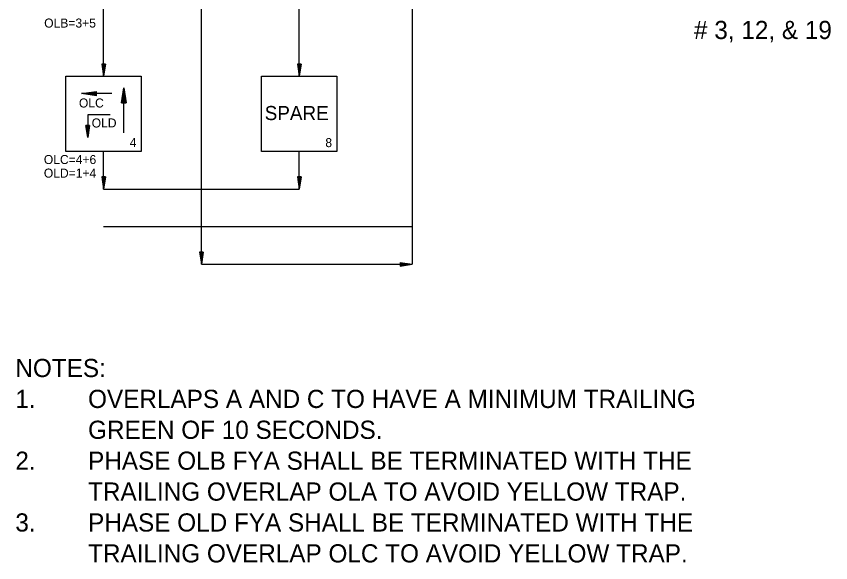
# Model space of a CAD drawing. Extents: x -218554 to 420030, y -566264 to -483460.
# Drawn here: x 418144.4 to 418332.6, y -565562.1 to -565435.8 of the extents above; entities that cross this region are included whole.
import ezdxf

# ---------------------------------------------------------------- set-up
doc = ezdxf.new("R2010")
doc.units = 0
doc.layers.add('G-ANNO-STMP', color=7, linetype='Continuous')
doc.layers.add('Level 57', color=7, linetype='Continuous')

msp = doc.modelspace()

# ---------------------------------------------------------------- linework, layer by layer
at = {"layer": 'Level 57'}
for p, q in [((418187.2, -565493.1), (418187.2, -565310.48)), ((418235.9, -565310.48), (418235.9, -565493.1)), ((418164.59, -565449.62), (418164.59, -565432.22)), ((418209.81, -565449.62), (418209.81, -565432.22)), ((418164.18, -565446.83), (418164.59, -565449.62)), ((418165.01, -565446.83), (418164.18, -565446.83)), ((418164.25, -565446.83), (418164.59, -565449.15)), ((418164.32, -565446.83), (418164.59, -565448.67)), ((418164.39, -565446.83), (418164.59, -565448.21)), ((418164.46, -565446.83), (418164.59, -565447.74)), ((418164.53, -565446.83), (418164.59, -565447.27)), ((418165.01, -565446.83), (418164.59, -565449.62)), ((418164.73, -565446.83), (418164.59, -565447.74)), ((418164.87, -565446.83), (418164.59, -565448.67)), ((418164.94, -565446.83), (418164.59, -565449.15)), ((418164.8, -565446.83), (418164.59, -565448.21)), ((418164.66, -565446.83), (418164.59, -565447.27)), ((418209.4, -565446.83), (418209.81, -565449.62)), ((418210.23, -565446.83), (418209.4, -565446.83)), ((418209.47, -565446.83), (418209.81, -565449.15)), ((418209.54, -565446.83), (418209.81, -565448.67)), ((418209.61, -565446.83), (418209.81, -565448.21)), ((418209.68, -565446.83), (418209.81, -565447.74)), ((418209.75, -565446.83), (418209.81, -565447.27)), ((418210.23, -565446.83), (418209.81, -565449.62)), ((418209.95, -565446.83), (418209.81, -565447.74)), ((418210.09, -565446.83), (418209.81, -565448.67)), ((418210.16, -565446.83), (418209.81, -565449.15)), ((418210.02, -565446.83), (418209.81, -565448.21)), ((418209.88, -565446.83), (418209.81, -565447.27)), ((418168.75, -565455.76), (418169.28, -565452.29)), ((418169.28, -565462.72), (418169.28, -565452.29)), ((418169.28, -565452.29), (418169.8, -565455.76)), ((418159.46, -565453.65), (418162.94, -565453.13)), ((418166.51, -565453.65), (418159.46, -565453.65)), ((418162.94, -565454.17), (418159.46, -565453.65)), ((418162.94, -565453.22), (418160.04, -565453.65)), ((418160.04, -565453.65), (418162.94, -565454.09)), ((418160.64, -565453.65), (418162.94, -565453.31)), ((418162.94, -565454), (418160.64, -565453.65)), ((418162.94, -565453.39), (418161.22, -565453.65)), ((418161.22, -565453.65), (418162.94, -565453.91)), ((418161.8, -565453.65), (418162.94, -565453.48)), ((418162.94, -565453.82), (418161.8, -565453.65)), ((418162.94, -565453.57), (418162.39, -565453.65)), ((418162.39, -565453.65), (418162.94, -565453.73)), ((418162.94, -565454.17), (418162.94, -565453.13)), ((418169.28, -565452.87), (418168.84, -565455.76)), ((418168.93, -565455.76), (418169.28, -565453.47)), ((418169.28, -565454.04), (418169.02, -565455.76)), ((418169.71, -565455.76), (418169.28, -565452.87)), ((418169.28, -565453.47), (418169.62, -565455.76)), ((418169.53, -565455.76), (418169.28, -565454.04)), ((418168.75, -565455.76), (418169.8, -565455.76)), ((418169.11, -565455.76), (418169.28, -565454.63)), ((418169.28, -565455.21), (418169.19, -565455.76)), ((418169.28, -565454.63), (418169.45, -565455.76)), ((418169.36, -565455.76), (418169.28, -565455.21)), ((418166.15, -565458.59), (418160.93, -565458.59)), ((418160.93, -565458.59), (418160.93, -565463.81)), ((418160.93, -565463.81), (418160.51, -565461.02)), ((418161.35, -565461.02), (418160.51, -565461.02)), ((418160.58, -565461.02), (418160.93, -565463.34)), ((418160.93, -565462.86), (418160.66, -565461.02)), ((418160.72, -565461.02), (418160.93, -565462.4)), ((418160.93, -565461.93), (418160.8, -565461.02)), ((418160.87, -565461.02), (418160.93, -565461.46)), ((418160.93, -565461.46), (418161, -565461.02)), ((418161.07, -565461.02), (418160.93, -565461.93)), ((418160.93, -565462.4), (418161.14, -565461.02)), ((418161.21, -565461.02), (418160.93, -565462.86)), ((418160.93, -565463.34), (418161.28, -565461.02)), ((418161.35, -565461.02), (418160.93, -565463.81)), ((418164.59, -565475.7), (418164.59, -565467.01)), ((418209.81, -565475.7), (418209.81, -565467.01)), ((418209.81, -565475.7), (418209.81, -565467.01)), ((418164.18, -565472.92), (418164.59, -565475.7)), ((418165.01, -565472.92), (418164.18, -565472.92)), ((418164.25, -565472.92), (418164.59, -565475.24)), ((418164.32, -565472.92), (418164.59, -565474.76)), ((418164.39, -565472.92), (418164.59, -565474.3)), ((418164.46, -565472.92), (418164.59, -565473.83)), ((418164.53, -565472.92), (418164.59, -565473.36)), ((418165.01, -565472.92), (418164.59, -565475.7)), ((418164.73, -565472.92), (418164.59, -565473.83)), ((418164.87, -565472.92), (418164.59, -565474.76)), ((418164.94, -565472.92), (418164.59, -565475.24)), ((418164.8, -565472.92), (418164.59, -565474.3)), ((418164.66, -565472.92), (418164.59, -565473.36)), ((418209.4, -565472.92), (418209.81, -565475.7)), ((418210.23, -565472.92), (418209.4, -565472.92)), ((418209.4, -565472.92), (418209.81, -565475.7)), ((418210.23, -565472.92), (418209.4, -565472.92)), ((418209.47, -565472.92), (418209.81, -565475.24)), ((418209.47, -565472.92), (418209.81, -565475.24)), ((418209.54, -565472.92), (418209.81, -565474.76)), ((418209.54, -565472.92), (418209.81, -565474.76)), ((418209.61, -565472.92), (418209.81, -565474.3)), ((418209.61, -565472.92), (418209.81, -565474.3)), ((418209.68, -565472.92), (418209.81, -565473.83)), ((418209.68, -565472.92), (418209.81, -565473.83)), ((418209.75, -565472.92), (418209.81, -565473.36)), ((418209.75, -565472.92), (418209.81, -565473.36)), ((418210.23, -565472.92), (418209.81, -565475.7)), ((418209.95, -565472.92), (418209.81, -565473.83)), ((418210.09, -565472.92), (418209.81, -565474.76)), ((418210.16, -565472.92), (418209.81, -565475.24)), ((418210.02, -565472.92), (418209.81, -565474.3)), ((418209.88, -565472.92), (418209.81, -565473.36)), ((418210.23, -565472.92), (418209.81, -565475.7)), ((418209.95, -565472.92), (418209.81, -565473.83)), ((418210.09, -565472.92), (418209.81, -565474.76)), ((418210.16, -565472.92), (418209.81, -565475.24)), ((418210.02, -565472.92), (418209.81, -565474.3)), ((418209.88, -565472.92), (418209.81, -565473.36)), ((418164.59, -565475.7), (418209.81, -565475.7)), ((418164.59, -565484.4), (418235.9, -565484.4)), ((418186.79, -565490.31), (418187.2, -565493.1)), ((418187.62, -565490.31), (418186.79, -565490.31)), ((418186.86, -565490.31), (418187.2, -565492.63)), ((418186.93, -565490.31), (418187.2, -565492.15)), ((418187, -565490.31), (418187.2, -565491.69)), ((418187.07, -565490.31), (418187.2, -565491.22)), ((418187.14, -565490.31), (418187.2, -565490.75)), ((418187.62, -565490.31), (418187.2, -565493.1)), ((418187.34, -565490.31), (418187.2, -565491.22)), ((418187.48, -565490.31), (418187.2, -565492.15)), ((418187.55, -565490.31), (418187.2, -565492.63)), ((418187.41, -565490.31), (418187.2, -565491.69)), ((418187.27, -565490.31), (418187.2, -565490.75)), ((418187.2, -565493.1), (418235.9, -565493.1)), ((418233.12, -565492.68), (418235.9, -565493.1)), ((418233.12, -565492.68), (418233.12, -565493.51)), ((418233.12, -565492.75), (418235.44, -565493.1)), ((418233.12, -565492.82), (418234.96, -565493.1)), ((418233.12, -565492.89), (418234.49, -565493.1)), ((418233.12, -565492.96), (418234.02, -565493.1)), ((418233.12, -565493.03), (418233.56, -565493.1)), ((418233.12, -565493.51), (418235.9, -565493.1)), ((418233.12, -565493.23), (418234.02, -565493.1)), ((418233.12, -565493.37), (418234.96, -565493.1)), ((418233.12, -565493.44), (418235.44, -565493.1)), ((418233.12, -565493.3), (418234.49, -565493.1)), ((418233.12, -565493.16), (418233.56, -565493.1))]:
    msp.add_line(p, q, dxfattribs=at)
for points in [[(418155.9, -565449.62), (418173.29, -565449.62), (418173.29, -565467.01), (418155.9, -565467.01)], [(418201.12, -565449.62), (418218.51, -565449.62), (418218.51, -565467.01), (418201.12, -565467.01)]]:
    msp.add_lwpolyline(points, close=True, dxfattribs=at)

# ---------------------------------------------------------------- texts
at = {"layer": 'G-ANNO-STMP'}
for s, p in [('# 3, 12, & 19', (418301.04, -565441.04)), ('NOTES:', (418144.21, -565519.17)), ('1.', (418144.21, -565526.31)), ('OVERLAPS A AND C TO HAVE A MINIMUM TRAILING', (418161.01, -565526.31)), ('GREEN OF 10 SECONDS.', (418161.01, -565533.45)), ('2.', (418144.21, -565540.59)), ('PHASE OLB FYA SHALL BE TERMINATED WITH THE', (418161.01, -565540.59)), ('TRAILING OVERLAP OLA TO AVOID YELLOW TRAP.', (418161.01, -565547.73)), ('3.', (418144.21, -565554.87)), ('PHASE OLD FYA SHALL BE TERMINATED WITH THE ', (418161.01, -565554.87)), ('TRAILING OVERLAP OLC TO AVOID YELLOW TRAP.', (418161.01, -565562.01))]:
    msp.add_text(s, height=4.2, dxfattribs=at).set_placement(p)
at = {"layer": 'Level 57'}
for s, height, p in [('OLB=3+5', 2.087, (418150.87, -565438.39)), ('OLC', 2.087, (418158.9, -565456.86)), ('SPARE', 3.261, (418201.83, -565459.77)), ('OLD', 2.087, (418161.85, -565461.48)), ('4', 2.09, (418170.62, -565466.02)), ('8', 2.09, (418215.84, -565466.02)), ('OLC=4+6', 2.087, (418150.79, -565469.93)), ('OLD=1+4', 2.087, (418150.79, -565473.07))]:
    msp.add_text(s, height=height, dxfattribs=at).set_placement(p)

doc.saveas('drawing.dxf')
